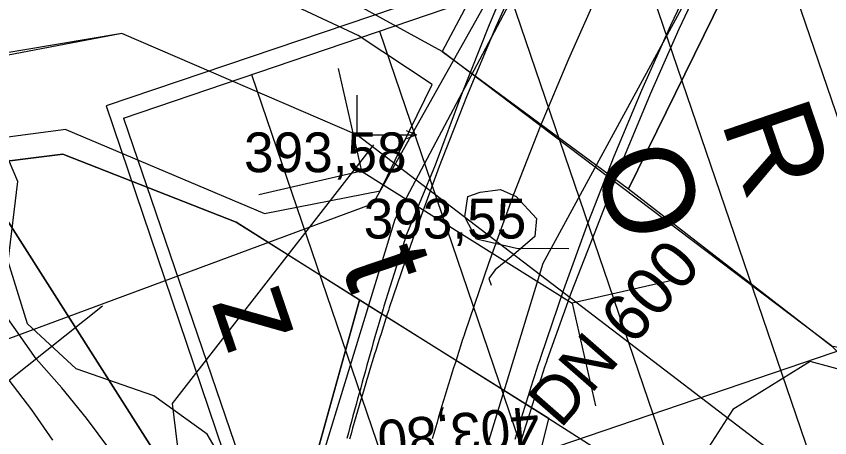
# Model space of a CAD drawing. Extents: x -574342 to -508101, y -1143544 to -1123894.
# Drawn here: x -508550.57 to -508530.11, y -1143176.99 to -1143166.39 of the extents above; entities that cross this region are included whole.
import ezdxf

# ---------------------------------------------------------------- set-up
doc = ezdxf.new("R2010")
doc.units = 0
for name, color, linetype in [('01_PARCELY_NAVRH_PC', 7, 'Continuous'), ('01_PARCELY_NAVRH_VHO', 7, 'Continuous'), ('01_PARCELY_NAVRH_ŽP', 7, 'Continuous'), ('05_VHO_V_TOK_STAV', 7, 'Continuous'), ('1000', 7, 'Continuous'), ('15', 7, 'Continuous'), ('21', 7, 'Continuous'), ('23', 7, 'Continuous'), ('37', 7, 'Continuous'), ('42', 7, 'Continuous'), ('52', 7, 'Continuous'), ('60', 7, 'Continuous'), ('Level 255', 7, 'Continuous'), ('Level24', 7, 'Continuous'), ('SO 101_popis oblouku', 7, 'Continuous'), ('tab', 7, 'Continuous'), ('VRST VEDL', 7, 'Continuous')]:
    doc.layers.add(name, color=color, linetype=linetype)

msp = doc.modelspace()

# ---------------------------------------------------------------- linework, layer by layer
msp.add_lwpolyline([(-508548.315, -1143168.642), (-508540.774, -1143190.92), (-508520.151, -1143183.94), (-508527.691, -1143161.661)], close=True)
at = {"layer": '01_PARCELY_NAVRH_PC'}
for points in [[(-508510.179, -1143116.058), (-508515.95, -1143130.65), (-508519.02, -1143135.54), (-508530.41, -1143150.9), (-508533.66, -1143155.6), (-508539.86, -1143167.27), (-508535.17, -1143170.73), (-508529.25, -1143158.67), (-508513.07, -1143136.47), (-508505.79, -1143121.37), (-508504.685, -1143116.058)], [(-508510.179, -1143116.058), (-508515.95, -1143130.65), (-508519.02, -1143135.54), (-508530.41, -1143150.9), (-508533.66, -1143155.6), (-508539.86, -1143167.27), (-508535.17, -1143170.73), (-508529.25, -1143158.67), (-508513.07, -1143136.47), (-508505.79, -1143121.37), (-508504.685, -1143116.058)], [(-508524.26, -1143263.08), (-508531.16, -1143250.06), (-508535.34, -1143238.37), (-508537.02, -1143231.11), (-508538.46, -1143221.35), (-508540.02, -1143209.35), (-508540.32, -1143193.28), (-508538.65, -1143182.46), (-508537.18, -1143176.51), (-508541.94, -1143173.53), (-508544.25, -1143181.83), (-508544.97, -1143188.3), (-508545.24, -1143191.32), (-508545.52, -1143198.58), (-508545.45, -1143205.07), (-508544.32, -1143217.47), (-508542.83, -1143228.38), (-508540.55, -1143238.43), (-508539.77, -1143241.25), (-508539.07, -1143243.44), (-508536.24, -1143250.83), (-508534.5, -1143254.93), (-508531.94, -1143260.32)], [(-508524.26, -1143263.08), (-508531.16, -1143250.06), (-508535.34, -1143238.37), (-508537.02, -1143231.11), (-508538.46, -1143221.35), (-508540.02, -1143209.35), (-508540.32, -1143193.28), (-508538.65, -1143182.46), (-508537.18, -1143176.51), (-508541.94, -1143173.53), (-508544.25, -1143181.83), (-508544.97, -1143188.3), (-508545.24, -1143191.32), (-508545.52, -1143198.58), (-508545.45, -1143205.07), (-508544.32, -1143217.47), (-508542.83, -1143228.38), (-508540.55, -1143238.43), (-508539.77, -1143241.25), (-508539.07, -1143243.44), (-508536.24, -1143250.83), (-508534.5, -1143254.93), (-508531.94, -1143260.32)]]:
    msp.add_lwpolyline(points, dxfattribs=at)
at = {"layer": '01_PARCELY_NAVRH_VHO'}
for points in [[(-508446.56, -1143243.12), (-508452.58, -1143244.39), (-508461.81, -1143244.49), (-508467.98, -1143243.62), (-508478.66, -1143222.38), (-508487.9, -1143213.8), (-508496.38, -1143198.1), (-508504.26, -1143191.1), (-508516.39, -1143188), (-508530.07, -1143174.68), (-508539.86, -1143167.27), (-508547.02, -1143163.34), (-508553.27, -1143164.53), (-508559.77, -1143166.35), (-508565.39, -1143163.91), (-508571.39, -1143166.22), (-508578.23, -1143159.53), (-508587.9, -1143163.05), (-508596.45, -1143153.64), (-508600.04, -1143155.89), (-508608.16, -1143150.99), (-508613.1, -1143145.09)], [(-508551.68, -1143170.14), (-508549.4, -1143169.86), (-508545.04, -1143171.57), (-508537.18, -1143176.51), (-508534.6, -1143178.15), (-508533.13, -1143181.54), (-508526.17, -1143187.6), (-508523.49, -1143191.39), (-508517.97, -1143196.35), (-508514.48, -1143199.68), (-508508.1, -1143200.58), (-508505.21, -1143200.49), (-508503.8, -1143201.12), (-508497.27, -1143211.29), (-508498.42, -1143216.3), (-508497.14, -1143220.02), (-508490.67, -1143220.8), (-508485.31, -1143225.73), (-508480.78, -1143231.64), (-508476.67, -1143241.6), (-508474.42, -1143249.95), (-508480.76, -1143258.08), (-508469.74, -1143257.73), (-508446.21, -1143255.76)]]:
    msp.add_lwpolyline(points, dxfattribs=at)
for points in [[(-508536.24, -1143250.83), (-508539.07, -1143243.44), (-508539.77, -1143241.25), (-508540.55, -1143238.43), (-508542.83, -1143228.38), (-508544.32, -1143217.47), (-508545.45, -1143205.07), (-508545.52, -1143198.58), (-508545.24, -1143191.32), (-508544.97, -1143188.3), (-508544.25, -1143181.83), (-508551.68, -1143170.14), (-508558.5, -1143170.32), (-508555.03, -1143173.64), (-508548.66, -1143186.8), (-508549.748, -1143197.559), (-508549.999, -1143204.321), (-508547.53, -1143223.9), (-508542.99, -1143242.68), (-508538.24, -1143253.15)], [(-508536.24, -1143250.83), (-508539.07, -1143243.44), (-508539.77, -1143241.25), (-508540.55, -1143238.43), (-508542.83, -1143228.38), (-508544.32, -1143217.47), (-508545.45, -1143205.07), (-508545.52, -1143198.58), (-508545.24, -1143191.32), (-508544.97, -1143188.3), (-508544.25, -1143181.83), (-508551.68, -1143170.14), (-508558.5, -1143170.32), (-508555.03, -1143173.64), (-508548.66, -1143186.8), (-508549.63, -1143198.15), (-508549.79, -1143203.71), (-508547.53, -1143223.9), (-508542.99, -1143242.68), (-508538.24, -1143253.15)]]:
    msp.add_lwpolyline(points, close=True, dxfattribs=at)
at = {"layer": '01_PARCELY_NAVRH_ŽP'}
for points in [[(-508504.685, -1143116.058), (-508505.79, -1143121.37), (-508513.07, -1143136.47), (-508529.25, -1143158.67), (-508535.17, -1143170.73), (-508530.07, -1143174.68), (-508525.32, -1143175.64), (-508523.79, -1143164.91), (-508521.99, -1143159.7), (-508510.09, -1143151.01), (-508503.75, -1143144.67), (-508499.11, -1143135.6), (-508498.41, -1143129.24), (-508498.01, -1143119.91), (-508496.906, -1143116.058)], [(-508649.66, -1143119.13), (-508584.79, -1143151.71), (-508539.57, -1143146.61), (-508530.41, -1143150.9), (-508533.66, -1143155.6), (-508539.86, -1143167.27), (-508547.02, -1143163.34), (-508553.27, -1143164.53), (-508559.77, -1143166.35), (-508565.39, -1143163.91), (-508571.39, -1143166.22), (-508578.23, -1143159.53), (-508587.9, -1143163.05), (-508596.45, -1143153.64), (-508600.04, -1143155.89), (-508608.16, -1143150.99), (-508613.1, -1143145.09)]]:
    msp.add_lwpolyline(points, dxfattribs=at)
msp.add_lwpolyline([(-508544.25, -1143181.83), (-508541.94, -1143173.53), (-508545.04, -1143171.57), (-508549.4, -1143169.86), (-508551.68, -1143170.14)], close=True, dxfattribs=at)
at = {"layer": '05_VHO_V_TOK_STAV'}
msp.add_lwpolyline([(-508447.49, -1143245.57), (-508453.89, -1143245.84), (-508469.84, -1143247.46), (-508476.067, -1143236.175), (-508482.77, -1143224.26), (-508489.11, -1143218.88), (-508496.94, -1143217.04), (-508494.75, -1143210.95), (-508502.24, -1143200.02), (-508504.69, -1143198.72), (-508508.04, -1143199.26), (-508513.72, -1143198.12), (-508516.16, -1143196.14), (-508515.31, -1143194.32), (-508517.287, -1143192.866), (-508519.733, -1143191.098), (-508522.24, -1143189.31), (-508524.27, -1143185.62), (-508530.674, -1143178.031), (-508542.01, -1143169.37), (-508547.92, -1143166.82), (-508560.33, -1143168.91)], dxfattribs=at)
at = {"layer": '1000'}
for points in [[(-508537.942, -1143164.859), (-508538.681, -1143166.6), (-508539.378, -1143168.358), (-508540.035, -1143170.13), (-508540.756, -1143171.879), (-508541.329, -1143173.681), (-508541.348, -1143173.747), (-508541.389, -1143173.889), (-508541.43, -1143174.031), (-508541.471, -1143174.172), (-508541.512, -1143174.314), (-508541.553, -1143174.456), (-508541.593, -1143174.598), (-508541.634, -1143174.739), (-508541.674, -1143174.881), (-508541.714, -1143175.023), (-508541.754, -1143175.165), (-508541.793, -1143175.307), (-508541.833, -1143175.449), (-508541.847, -1143175.499), (-508541.872, -1143175.591), (-508541.911, -1143175.733), (-508541.951, -1143175.875), (-508541.989, -1143176.017), (-508542.028, -1143176.159), (-508542.067, -1143176.302), (-508542.105, -1143176.444), (-508542.144, -1143176.586), (-508542.182, -1143176.728), (-508542.22, -1143176.871), (-508542.257, -1143177.013)], [(-508537.752, -1143164.947), (-508538.52, -1143166.67), (-508539.248, -1143168.411), (-508539.936, -1143170.168), (-508540.583, -1143171.94), (-508541.19, -1143173.727), (-508541.211, -1143173.792), (-508541.257, -1143173.932), (-508541.302, -1143174.072), (-508541.347, -1143174.212), (-508541.391, -1143174.352), (-508541.436, -1143174.493), (-508541.48, -1143174.633), (-508541.524, -1143174.774), (-508541.568, -1143174.914), (-508541.611, -1143175.055), (-508541.654, -1143175.195), (-508541.697, -1143175.336), (-508541.74, -1143175.477), (-508541.755, -1143175.527), (-508541.782, -1143175.618), (-508541.825, -1143175.759), (-508541.866, -1143175.9), (-508541.908, -1143176.041), (-508541.949, -1143176.182), (-508541.991, -1143176.324), (-508542.032, -1143176.465), (-508542.072, -1143176.607), (-508542.113, -1143176.748), (-508542.153, -1143176.89), (-508542.193, -1143177.031)], [(-508533.349, -1143164.995), (-508534.117, -1143166.617), (-508534.848, -1143168.256), (-508535.54, -1143169.912), (-508536.195, -1143171.583), (-508536.811, -1143173.269), (-508537.388, -1143174.969), (-508537.408, -1143175.031), (-508537.451, -1143175.164), (-508537.494, -1143175.297), (-508537.537, -1143175.43), (-508537.579, -1143175.564), (-508537.622, -1143175.697), (-508537.664, -1143175.831), (-508537.705, -1143175.964), (-508537.747, -1143176.098), (-508537.788, -1143176.232), (-508537.829, -1143176.366), (-508537.87, -1143176.5), (-508537.911, -1143176.634), (-508537.925, -1143176.681), (-508537.951, -1143176.768), (-508537.991, -1143176.902), (-508538.031, -1143177.036)], [(-508533.142, -1143165.095), (-508533.905, -1143166.714), (-508534.63, -1143168.35), (-508535.316, -1143170.003), (-508535.963, -1143171.671), (-508536.612, -1143173.339), (-508537.216, -1143175.025), (-508537.237, -1143175.086), (-508537.283, -1143175.218), (-508537.328, -1143175.351), (-508537.372, -1143175.483), (-508537.417, -1143175.616), (-508537.461, -1143175.748), (-508537.504, -1143175.881), (-508537.547, -1143176.014), (-508537.59, -1143176.147), (-508537.633, -1143176.28), (-508537.675, -1143176.413), (-508537.717, -1143176.546), (-508537.759, -1143176.679), (-508537.774, -1143176.727), (-508537.8, -1143176.813), (-508537.841, -1143176.946), (-508537.882, -1143177.08)], [(-508545.706, -1143185.093), (-508545.971, -1143183.719), (-508545.98, -1143182.718), (-508546.177, -1143181.751), (-508546.439, -1143180.799), (-508546.738, -1143179.853), (-508546.806, -1143179.653), (-508547.142, -1143178.949), (-508547.667, -1143178.107), (-508548.224, -1143177.29), (-508548.811, -1143176.501), (-508549.428, -1143175.74), (-508550.073, -1143175.007), (-508552.734, -1143171.235), (-508554.338, -1143169.098)]]:
    msp.add_lwpolyline(points, dxfattribs=at)
at = {"layer": '21'}
for points in [[(-508535.934, -1143165.782), (-508536.684, -1143167.463), (-508537.394, -1143169.161), (-508538.065, -1143170.875), (-508538.697, -1143172.605), (-508539.289, -1143174.348), (-508539.309, -1143174.411), (-508539.354, -1143174.548), (-508539.398, -1143174.685), (-508539.442, -1143174.821), (-508539.485, -1143174.958), (-508539.529, -1143175.095), (-508539.572, -1143175.232), (-508539.615, -1143175.369), (-508539.657, -1143175.506), (-508539.7, -1143175.643), (-508539.742, -1143175.781), (-508539.784, -1143175.918), (-508539.825, -1143176.055), (-508539.84, -1143176.104), (-508539.867, -1143176.193), (-508539.908, -1143176.33), (-508539.949, -1143176.468), (-508539.989, -1143176.606), (-508540.03, -1143176.743), (-508540.07, -1143176.881), (-508540.11, -1143177.019)], [(-508549.655, -1143177.055), (-508550.184, -1143176.289), (-508550.749, -1143175.547)]]:
    msp.add_lwpolyline(points, dxfattribs=at)
at = {"layer": '23'}
msp.add_lwpolyline([(-508550.749, -1143175.547), (-508548.405, -1143173.675)], dxfattribs=at)
at = {"layer": '37'}
msp.add_line((-508542.01, -1143169.37), (-508547.92, -1143166.82), dxfattribs=at)
msp.add_line((-508542.01, -1143169.37), (-508547.92, -1143166.82), dxfattribs=at)
for points in [[(-508544.44, -1143182.59), (-508541.04, -1143171.49), (-508533.03, -1143156.36), (-508515.99, -1143133.69), (-508511.59, -1143124.92)], [(-508544.44, -1143182.59), (-508541.04, -1143171.49), (-508533.03, -1143156.36), (-508515.99, -1143133.69), (-508511.59, -1143124.92)], [(-508547.92, -1143166.82), (-508553.16, -1143167.82), (-508560.33, -1143168.91), (-508565.27, -1143165.89), (-508574.31, -1143168.46), (-508577.98, -1143162.03), (-508590.48, -1143165.72), (-508598.91, -1143159.61), (-508613.15, -1143152.7), (-508619.64, -1143147.26), (-508621.96, -1143150.81), (-508636.38, -1143143.79), (-508640.58, -1143136.45), (-508648.26, -1143130.35), (-508659.04, -1143126.17), (-508667.83, -1143128.19), (-508687.89, -1143128.88), (-508696.93, -1143137.18), (-508703.096, -1143142.431)], [(-508547.92, -1143166.82), (-508553.16, -1143167.82), (-508560.33, -1143168.91), (-508565.27, -1143165.89), (-508574.31, -1143168.46), (-508577.98, -1143162.03), (-508590.48, -1143165.72), (-508598.91, -1143159.61), (-508613.15, -1143152.7), (-508619.64, -1143147.26), (-508621.96, -1143150.81), (-508636.38, -1143143.79), (-508640.58, -1143136.45), (-508648.26, -1143130.35), (-508659.04, -1143126.17), (-508667.83, -1143128.19), (-508687.89, -1143128.88), (-508696.93, -1143137.18), (-508703.096, -1143142.431)], [(-508508.39, -1143126.78), (-508512.62, -1143134.91), (-508529.52, -1143158.24), (-508537.33, -1143172.61), (-508540.68, -1143183.59)], [(-508508.39, -1143126.78), (-508512.62, -1143134.91), (-508529.52, -1143158.24), (-508537.33, -1143172.61), (-508540.68, -1143183.59)]]:
    msp.add_lwpolyline(points, dxfattribs=at)
at = {"layer": '42'}
msp.add_lwpolyline([(-508584.52, -1143185.46), (-508576.94, -1143184.13), (-508565.72, -1143180.04), (-508541.6, -1143171.1), (-508528.13, -1143147.12), (-508515.55, -1143126.37), (-508515.51, -1143116.058)], dxfattribs=at)
msp.add_lwpolyline([(-508584.52, -1143185.46), (-508576.94, -1143184.13), (-508565.72, -1143180.04), (-508541.6, -1143171.1), (-508528.13, -1143147.12), (-508515.55, -1143126.37), (-508515.51, -1143116.058)], dxfattribs=at)
at = {"layer": '52'}
for p, q in [((-508542.01, -1143168.37), (-508542.01, -1143169.37)), ((-508542.01, -1143169.37), (-508540.51, -1143169.37)), ((-508540.51, -1143169.37), (-508540.76, -1143169.27)), ((-508540.51, -1143169.37), (-508540.76, -1143169.47))]:
    msp.add_line(p, q, dxfattribs=at)
at = {"layer": '60'}
for points in [[(-508549.33, -1143169.24), (-508554.03, -1143169.86), (-508560.83, -1143169.76), (-508569.44, -1143175.37), (-508585.17, -1143175.34), (-508593.54, -1143172.04), (-508609.76, -1143164.75), (-508620.02, -1143158.01), (-508636.47, -1143152.72), (-508644.49, -1143147.03), (-508652.28, -1143139.28), (-508663.38, -1143137.35), (-508689.1, -1143144.32), (-508695.18, -1143142.29), (-508703.02, -1143158.17), (-508703.096, -1143158.256)], [(-508549.33, -1143169.24), (-508554.03, -1143169.86), (-508560.83, -1143169.76), (-508569.44, -1143175.37), (-508585.17, -1143175.34), (-508593.54, -1143172.04), (-508609.76, -1143164.75), (-508620.02, -1143158.01), (-508636.47, -1143152.72), (-508644.49, -1143147.03), (-508652.28, -1143139.28), (-508663.38, -1143137.35), (-508689.1, -1143144.32), (-508695.18, -1143142.29), (-508703.02, -1143158.17), (-508703.096, -1143158.256)], [(-508549.33, -1143169.24), (-508544.33, -1143171.35), (-508541.42, -1143170.78), (-508540.11, -1143168.1), (-508541.97, -1143166.87), (-508547.52, -1143164.27)], [(-508549.33, -1143169.24), (-508544.33, -1143171.35), (-508541.42, -1143170.78), (-508540.11, -1143168.1), (-508541.97, -1143166.87), (-508547.52, -1143164.27)], [(-508525.16, -1143176.55), (-508530.6, -1143175.07), (-508532.55, -1143176.28), (-508533.83, -1143178.28), (-508532.4, -1143181.41), (-508525.65, -1143187.42), (-508523.14, -1143191), (-508516.45, -1143194.78), (-508517.33, -1143196.24), (-508514.08, -1143199.23), (-508507.94, -1143200.06), (-508504.93, -1143199.98), (-508503.26, -1143200.81), (-508496.6, -1143211.46), (-508497.83, -1143216.41), (-508496.7, -1143219.56), (-508489.97, -1143220.34), (-508484.25, -1143225.74), (-508480.17, -1143231.74), (-508475.87, -1143242.05), (-508473.98, -1143249.93), (-508471.29, -1143252.95)], [(-508525.16, -1143176.55), (-508530.6, -1143175.07), (-508532.55, -1143176.28), (-508533.83, -1143178.28), (-508532.4, -1143181.41), (-508525.65, -1143187.42), (-508523.14, -1143191), (-508516.45, -1143194.78), (-508517.33, -1143196.24), (-508514.08, -1143199.23), (-508507.94, -1143200.06), (-508504.93, -1143199.98), (-508503.26, -1143200.81), (-508496.6, -1143211.46), (-508497.83, -1143216.41), (-508496.7, -1143219.56), (-508489.97, -1143220.34), (-508484.25, -1143225.74), (-508480.17, -1143231.74), (-508475.87, -1143242.05), (-508473.98, -1143249.93), (-508471.29, -1143252.95)]]:
    msp.add_lwpolyline(points, dxfattribs=at)
at = {"layer": 'Level24'}
for points in [[(-508542.48, -1143167.703), (-508541.888, -1143170.288), (-508544.472, -1143170.88)], [(-508541.888, -1143170.288), (-508536.593, -1143173.608)], [(-508534.008, -1143173.016), (-508536.593, -1143173.608), (-508536.001, -1143176.193)]]:
    msp.add_lwpolyline(points, dxfattribs=at)
at = {"layer": 'SO 101_popis oblouku'}
for p, q in [((-508547.874, -1143168.952), (-508531.782, -1143163.468)), ((-508531.782, -1143163.468), (-508524.47, -1143184.922)), ((-508535.001, -1143164.564), (-508527.689, -1143186.019)), ((-508538.219, -1143165.661), (-508530.907, -1143187.116)), ((-508541.437, -1143166.758), (-508534.125, -1143188.213)), ((-508544.655, -1143167.855), (-508537.343, -1143189.31)), ((-508547.874, -1143168.952), (-508540.562, -1143190.406)), ((-508544.218, -1143179.679), (-508528.126, -1143174.195))]:
    msp.add_line(p, q, dxfattribs=at)
msp.add_lwpolyline([(-508536.671, -1143172.241), (-508537.989, -1143172.23), (-508538.998, -1143171.993), (-508539.291, -1143171.432), (-508539.215, -1143170.925), (-508538.901, -1143170.811), (-508538.39, -1143170.742), (-508538.003, -1143170.923), (-508537.485, -1143171.476), (-508537.533, -1143171.926), (-508538.124, -1143172.437), (-508538.524, -1143172.769), (-508538.689, -1143172.983), (-508538.63, -1143173.156)], dxfattribs=at)
at = {"layer": 'tab'}
msp.add_lwpolyline([(-508541.589, -1143169.619), (-508546.652, -1143176.131), (-508545.652, -1143184.319)], dxfattribs=at)
at = {"layer": 'VRST VEDL'}
msp.add_lwpolyline([(-508545.031, -1143178.161), (-508545.771, -1143176.904), (-508547.118, -1143175.935), (-508549.071, -1143175.255), (-508550.291, -1143174.129), (-508550.778, -1143172.558), (-508550.532, -1143170.542), (-508551.524, -1143168.228)], dxfattribs=at)

# ---------------------------------------------------------------- texts
at = {"layer": '15'}
msp.add_text('DN 600', height=1.2, rotation=48.816, dxfattribs=at).set_placement((-508536.885, -1143176.787))
msp.add_text('DN 600', height=1.2, rotation=48.816, dxfattribs=at).set_placement((-508536.885, -1143176.787))
at = {"layer": 'Level 255'}
for s, p in [('393,58', (-508544.845, -1143170.31)), ('393,55', (-508541.835, -1143171.98))]:
    msp.add_text(s, height=1, dxfattribs=at).set_placement(p)
msp.add_text('403,80', height=1, rotation=185.2631, dxfattribs=at).set_placement((-508537.456, -1143176.196))
at = {"layer": 'SO 101_popis oblouku'}
for s, p in [('R', (-508532.859, -1143169.023)), ('O', (-508536.112, -1143170.018)), ('t', (-508542.41, -1143172.62)), ('z', (-508545.68, -1143173.563))]:
    msp.add_text(s, height=2.267, rotation=288.8145, dxfattribs=at).set_placement(p)

doc.saveas('drawing.dxf')
